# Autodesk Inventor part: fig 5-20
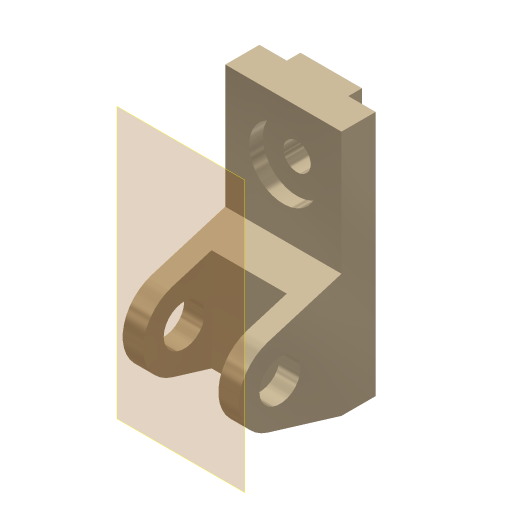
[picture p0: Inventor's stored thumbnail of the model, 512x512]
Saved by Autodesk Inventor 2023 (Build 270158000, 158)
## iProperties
Created: 2001-11
Part Number: fig 5-20
Document SubType Name: Modeling
Designer: Renu Muthoo
Density: 1 g/cm^3
Material: Generic
Appearance: Metal-Titanium (Polished)
Control State: 0
Master: False
Checked Out: False
Shininess: 65.0
Angle Display Precision: 2
Document Length Units: 11269
Document Angle Units: 11279
Document Time Units: 11290
Document Mass Units: 11283
Document Length Units Precision: 3
Document Angle Units Precision: 2
Compacted: False
Density: 0.0
Volumn: 0.0
Area: 0.0
PropertySet Name: Model Information
Author: Renu Muthoo
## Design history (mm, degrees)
node "Sketch1"
sketch "Sketch2"
  geometry: L1 (33.257, 104.664)-(33.257, -75.336); L2 (33.257, -75.336)-(8.257, -75.336); L3 (8.257, -75.336)-(-45.451, -59.045); L4 (-45.451, -1.628)-(8.257, 14.664); L5 (8.257, 14.664)-(8.257, 104.664); L6 (8.257, 104.664)-(33.257, 104.664); C1 r 15 at (-36.743, -30.336); A1 r 30 centre (-36.743, -30.336) between (-45.451, -1.628) and (-45.451, -59.045)
  constraints: 12 end point, 2 centre point, 2 equal length, 2 parallel, 2 point on circle, 2 tangent, 1 coincident, 1 perpendicular, 1 vertical
  dimensions: "d0" = 180 distance of L1.start L1.end; "d1" = 30 radius of A1; "d2" = 25 distance of L5.end L1.start; "d3" = 45 distance from line of L2 A1.centre; "d4" = 70 distance from line of L1 A1.centre; "d5" = 30 diameter of C1
extrude "Extrusion1" new body sketch "Sketch2" distance "d6" = 85; taper "d7" = 0 deg
workplane "Work Plane1"
sketch "Sketch3"
  geometry: L1 (15, 62.364)-(70, 62.364); L2 (70, 62.364)-(70, -52.386); L3 (70, -52.386)-(15, -52.386); L4 (15, -52.386)-(15, 62.364); L5 (0, -45)-(0, -28.708) reference
  constraints: 8 end point, 2 parallel, 1 horizontal, 1 perpendicular
  dimensions: "d8" = 55 distance of L1.start L1.end; "d9" = 15 distance between parallel lines of L5 L4
extrude "Extrusion2" cut sketch "Sketch3" distance "d10" = 50; taper "d11" = 0 deg
sketch "Sketch4"
  geometry: L1 (0, 25)-(85, 25) reference; L2 (0, 0)-(0, 25) reference; L3 (20, 25)-(65, 25); L4 (65, 25)-(65, 35); L5 (65, 35)-(20, 35); L6 (20, 35)-(20, 25)
  constraints: 8 end point, 2 parallel, 1 horizontal, 1 perpendicular, 1 point on line
  dimensions: "d12" = 45 distance of L4.end L5.end; "d13" = 10 distance of L3.end L4.end; "d14" = 20 distance between parallel lines of L2 L6
extrude "Extrusion3" join sketch "Sketch4" stored distance "d15" = 50; taper "d16" = 0 deg
sketch "Sketch5"
  geometry: L1 (85, 0)-(85, 90) reference; L2 (0, 90)-(85, 90) reference; 1 further point
  dimensions: "d17" = 42 distance from line of L2 point (42.5, 48); "d18" = 42.5 distance from line of L1 point (42.5, 48)
hole "Hole1" sketch "Sketch5" at (42.5, 48) diameter "d19" = 20; stored, may be unused: countersink angle "d23" = 82 deg, drill point angle "d25" = 118 deg; dims "d20" = 6, "d21" = 50, "d22" = 10, "d24" = 8
workplane "Work Plane10"
body "Solid1"
